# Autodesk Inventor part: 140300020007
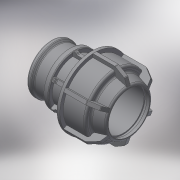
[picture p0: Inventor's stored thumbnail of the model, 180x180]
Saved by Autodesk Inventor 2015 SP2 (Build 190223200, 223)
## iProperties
Created: 2017-08
Part Number: 140300020007
Material: Generic
Description: PLASSON L.14 FEMALE ADAPTOR (SILVER) 20-3/4"
Document SubType Name: Modeling
Designer: KIM
Density: 1 g/cm^3
Appearance: Default
Author: KIM
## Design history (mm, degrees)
derived "140300.ipt"
feature "Solid1::140300.ipt"
tag "TaggingFeature1"
body "Solid1"
other parameters: "d2" = 51, "d4" = 15 deg, "d5" = 33.66, "d6" = 11.1078, "d9" = 24.117, "d10" = 42, "d11" = 31.3521, "d12" = 28.9404, "d13" = 33.7638, "d14" = 19, "d16" = 20.4, "d17" = 2.55, "d18" = 72, "d19" = 5.7, "d20" = 135 deg, "d21" = 5.7, "d22" = 28.9404, "d23" = 18, "d24" = 2.55, "d25" = 37.8, "d26" = 31.5, "d27" = 2.55, "d28" = 135 deg, "d29" = 1.53, "d31" = 1, "d44" = 0.4, "d45" = 0.6, "d46" = 150 deg, "d49" = 2.1, "d50" = 0, "d51" = 0.42, "d52" = 0.84, "d53" = 45 deg, "d55" = 6.356, "d56" = 2.1, "d57" = 0, "d58" = 0.6, "d61" = 360 deg, "G_" = 24.117, "E_" = 42, "H_" = 72, "l_" = 51, "l_2" = 19, "d54" = 15.89
